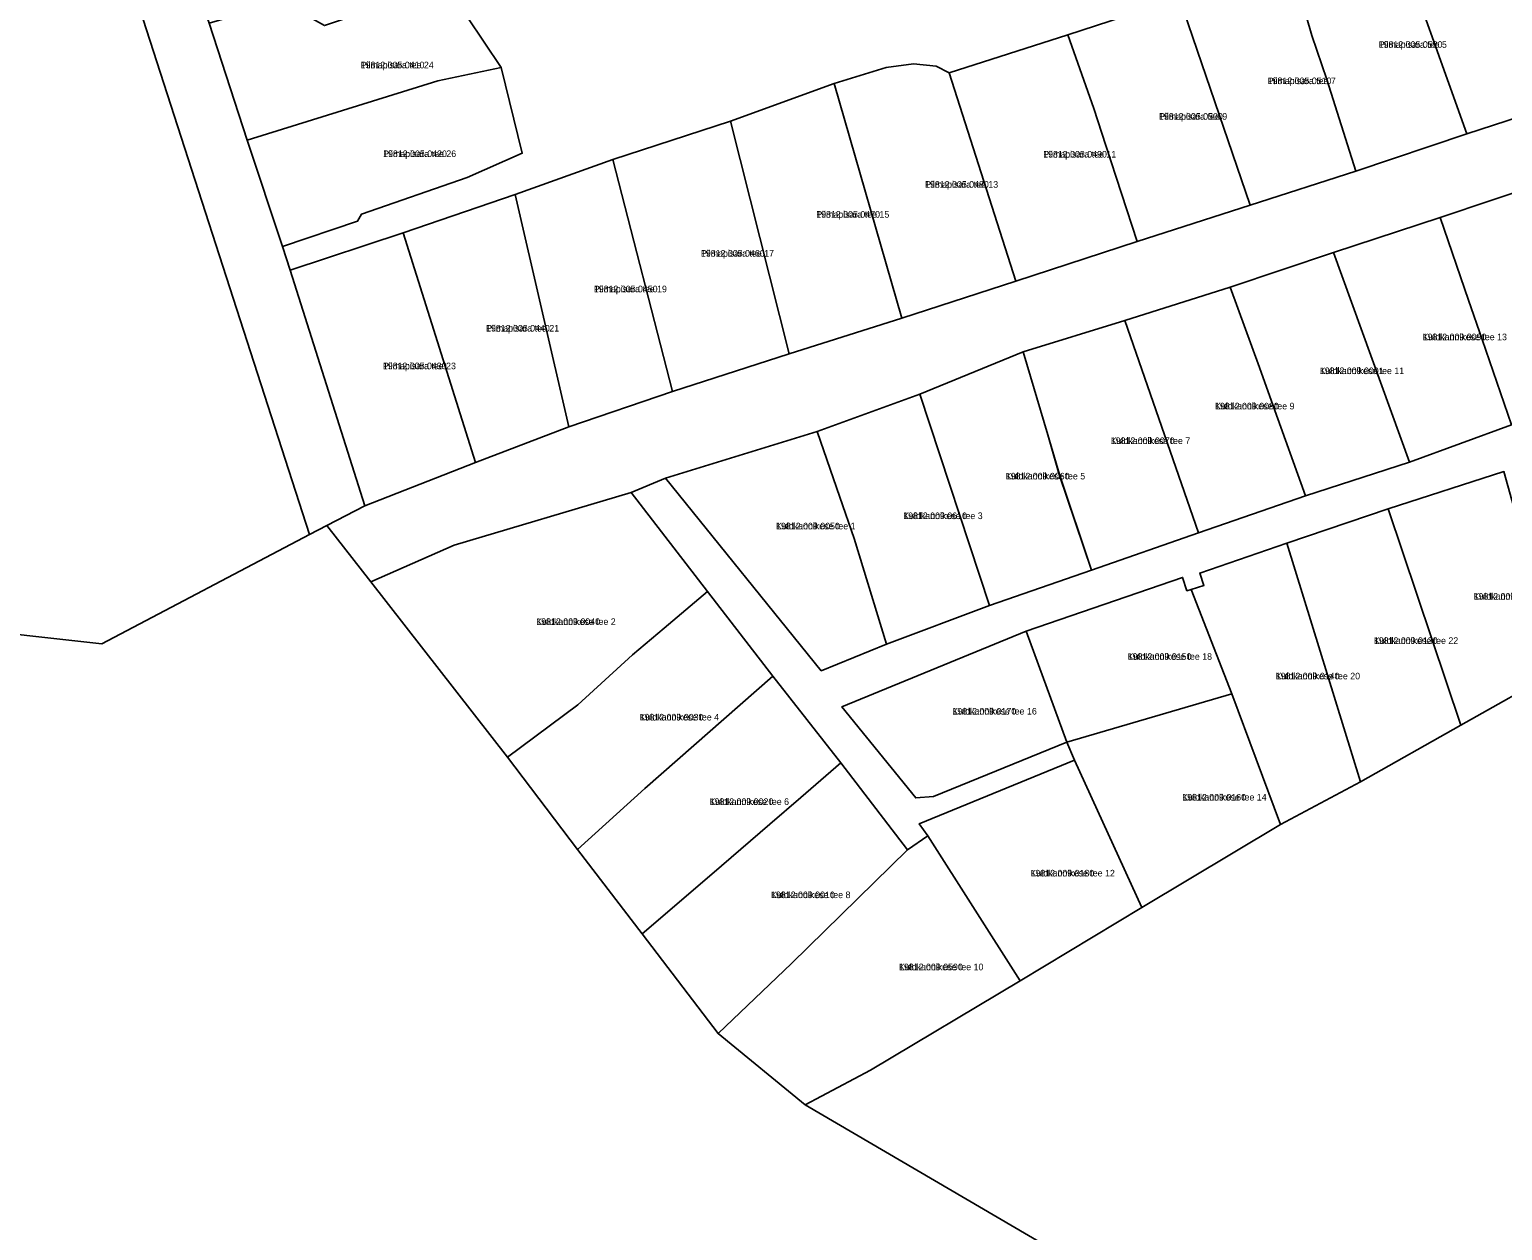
# Model space of a CAD drawing. Extents: x 516875 to 535633, y 6574491 to 6593094.
# Drawn here: x 517287.6 to 517622.6, y 6585054.3 to 6585327.5 of the extents above; entities that cross this region are included whole.
import ezdxf

# ---------------------------------------------------------------- set-up
doc = ezdxf.new("R2010")
doc.units = 0
for name, color, linetype in [('L_AADRESS', 7, 'Continuous'), ('PIIR', 7, 'Continuous'), ('TUNNUS', 7, 'Continuous')]:
    doc.layers.add(name, color=color, linetype=linetype)

msp = doc.modelspace()

# ---------------------------------------------------------------- linework, layer by layer
at = {"layer": 'PIIR'}
for points in [[(517363.93, 6585219.13), (517355.29, 6585214.67), (517351.33, 6585212.62), (517306.35, 6585351.92), (517308.83, 6585354.33), (517306.67, 6585359.47), (517261.59, 6585466.48), (517271.21, 6585468.82), (517305.11, 6585387.97), (517314.63, 6585364.95), (517317.95, 6585359.12), (517328.47, 6585328.95), (517337.16, 6585302.33), (517345.14, 6585278.12), (517346.9, 6585272.74)], [(517038.61, 6585356.85), (517061.8, 6585364.36), (517066.51, 6585412.44), (517103.89, 6585423.94), (517151.32, 6585438.55), (517221.5, 6585456.72), (517281.21, 6585332.08), (517282.72, 6585328.92), (517306.35, 6585351.92), (517351.33, 6585212.62), (517304.11, 6585187.79), (517235.26, 6585195.4), (517074.05, 6585291.89), (517021.05, 6585351.17)], [(517597.74, 6585350.7), (517621.4, 6585358.58), (517639.03, 6585311.71), (517614.54, 6585303.75)], [(517582.66, 6585316.09), (517579.3, 6585326.14), (517574.43, 6585343.02), (517597.74, 6585350.7), (517614.54, 6585303.75), (517589.29, 6585295.29)], [(517549.17, 6585334.61), (517574.43, 6585343.02), (517579.3, 6585326.14), (517582.66, 6585316.09), (517589.29, 6585295.29), (517565.22, 6585287.56)], [(517328.47, 6585328.95), (517348.36, 6585334.67), (517349.4, 6585331.37), (517354.69, 6585328.38), (517374.47, 6585334.99), (517387.15, 6585330.4), (517394.88, 6585318.83), (517380.48, 6585315.81), (517337.16, 6585302.33)], [(517532.39, 6585301.12), (517529.67, 6585309.52), (517523.81, 6585326.29), (517549.17, 6585334.61), (517565.22, 6585287.56), (517539.53, 6585279.24)], [(517496.81, 6585317.64), (517523.81, 6585326.29), (517529.67, 6585309.52), (517532.39, 6585301.12), (517539.53, 6585279.24), (517511.97, 6585270.23)], [(517470.66, 6585315.23), (517482.46, 6585318.86), (517488.71, 6585319.72), (517493.8, 6585319.19), (517496.81, 6585317.64), (517511.97, 6585270.23), (517486.02, 6585261.85)], [(517362.24, 6585283.93), (517345.14, 6585278.12), (517337.16, 6585302.33), (517380.48, 6585315.81), (517394.88, 6585318.83), (517399.68, 6585299.36), (517387.18, 6585293.81), (517363.13, 6585285.46)], [(517447.09, 6585306.65), (517470.66, 6585315.23), (517486.02, 6585261.85), (517460.4, 6585253.69)], [(517420.27, 6585297.94), (517447.09, 6585306.65), (517460.4, 6585253.69), (517433.9, 6585245.12)], [(517398.07, 6585289.93), (517420.27, 6585297.94), (517433.9, 6585245.12), (517410.31, 6585237.13)], [(517614.91, 6585265.96), (517608.44, 6585284.76), (517631.99, 6585292.6), (517648.45, 6585245.74), (517624.71, 6585237.55), (517618.01, 6585256.96)], [(517372.63, 6585281.26), (517398.07, 6585289.93), (517410.31, 6585237.13), (517389.09, 6585228.98)], [(517601.46, 6585229.09), (517584.2, 6585276.78), (517608.44, 6585284.76), (517614.91, 6585265.96), (517618.01, 6585256.96), (517624.71, 6585237.55)], [(517372.63, 6585281.26), (517389.09, 6585228.98), (517363.93, 6585219.13), (517346.9, 6585272.74)], [(517584.2, 6585276.78), (517601.46, 6585229.09), (517577.8, 6585221.42), (517570.49, 6585241.91), (517567.36, 6585250.58), (517560.73, 6585268.9)], [(517553.48, 6585213.04), (517536.73, 6585261.33), (517560.73, 6585268.9), (517567.36, 6585250.58), (517570.49, 6585241.91), (517577.8, 6585221.42)], [(517519.23, 6585235.31), (517513.62, 6585254.14), (517536.73, 6585261.33), (517553.48, 6585213.04), (517529.19, 6585204.53), (517521.91, 6585226.3)], [(517505.93, 6585196.48), (517490.14, 6585244.53), (517513.62, 6585254.14), (517519.23, 6585235.31), (517521.83, 6585226.3), (517529.19, 6585204.53)], [(517471.91, 6585221.15), (517466.75, 6585236.09), (517490.14, 6585244.53), (517505.93, 6585196.48), (517482.54, 6585187.67), (517475.16, 6585211.75)], [(517467.69, 6585181.64), (517432.31, 6585225.47), (517466.75, 6585236.09), (517471.91, 6585221.15), (517475.16, 6585211.75), (517482.54, 6585187.67)], [(517613.18, 6585169.29), (517596.62, 6585218.49), (517622.95, 6585226.93), (517635.49, 6585181.83)], [(517365.25, 6585201.88), (517384.23, 6585210.19), (517424.46, 6585222.17), (517441.82, 6585199.64), (517431.98, 6585191.3), (517424.8, 6585185.24), (517412.37, 6585173.91), (517396.34, 6585161.95)], [(517590.31, 6585156.36), (517573.58, 6585210.64), (517596.62, 6585218.49), (517613.18, 6585169.29)], [(517554.73, 6585200.99), (517553.8, 6585203.86), (517573.58, 6585210.64), (517590.31, 6585156.36), (517572.14, 6585146.66), (517561.08, 6585176.41), (517551.81, 6585200.13)], [(517523.54, 6585165.38), (517514.34, 6585190.62), (517549.87, 6585202.86), (517550.85, 6585199.83), (517551.81, 6585200.13), (517561.08, 6585176.41)], [(517396.34, 6585161.95), (517412.37, 6585173.91), (517424.8, 6585185.24), (517431.98, 6585191.3), (517441.82, 6585199.64), (517456.69, 6585180.4), (517427.6, 6585154.82), (517412.29, 6585140.99)], [(517489.18, 6585152.72), (517472.39, 6585173.45), (517514.34, 6585190.62), (517523.54, 6585165.38), (517493.26, 6585153.01)], [(517426.96, 6585121.82), (517412.29, 6585140.99), (517427.6, 6585154.82), (517456.69, 6585180.4), (517472.17, 6585160.72), (517463.07, 6585152.81), (517456.03, 6585146.73), (517442.8, 6585135.36)], [(517525.32, 6585161.27), (517523.54, 6585165.38), (517561.08, 6585176.41), (517572.14, 6585146.66), (517540.61, 6585127.8)], [(517487.31, 6585140.87), (517460.95, 6585115.01), (517444.25, 6585099.1), (517426.96, 6585121.82), (517442.8, 6585135.36), (517456.03, 6585146.73), (517463.07, 6585152.81), (517472.17, 6585160.72)], [(517491.97, 6585144.08), (517489.97, 6585146.82), (517525.32, 6585161.27), (517540.61, 6585127.8), (517512.94, 6585111.09)], [(517464.03, 6585082.92), (517444.25, 6585099.1), (517460.95, 6585115.01), (517487.31, 6585140.87), (517491.97, 6585144.08), (517512.94, 6585111.09), (517478.89, 6585090.76)]]:
    msp.add_lwpolyline(points, close=True, dxfattribs=at)
for points in [[(517549.17, 6585334.61), (517523.81, 6585326.29), (517496.81, 6585317.64), (517493.8, 6585319.19), (517488.71, 6585319.72), (517482.46, 6585318.86), (517470.66, 6585315.23), (517447.09, 6585306.65), (517420.27, 6585297.94), (517398.07, 6585289.93), (517372.63, 6585281.26), (517346.9, 6585272.74), (517345.14, 6585278.12), (517362.24, 6585283.93), (517363.13, 6585285.46), (517387.18, 6585293.81), (517399.68, 6585299.36), (517394.88, 6585318.83), (517387.15, 6585330.4)], [(517631.99, 6585292.6), (517608.44, 6585284.76), (517584.2, 6585276.78), (517560.73, 6585268.9), (517536.73, 6585261.33), (517513.62, 6585254.14), (517490.14, 6585244.53), (517466.75, 6585236.09), (517432.31, 6585225.47), (517424.46, 6585222.17), (517384.23, 6585210.19), (517365.25, 6585201.88), (517355.29, 6585214.67), (517363.93, 6585219.13), (517389.09, 6585228.98), (517410.31, 6585237.13), (517433.9, 6585245.12), (517460.4, 6585253.69), (517486.02, 6585261.85), (517511.97, 6585270.23), (517539.53, 6585279.24), (517565.22, 6585287.56), (517589.29, 6585295.29), (517614.54, 6585303.75), (517639.03, 6585311.71)], [(517622.95, 6585226.93), (517596.62, 6585218.49), (517573.58, 6585210.64), (517553.8, 6585203.86), (517554.73, 6585200.99), (517551.81, 6585200.13), (517550.85, 6585199.83), (517549.87, 6585202.86), (517514.34, 6585190.62), (517472.39, 6585173.45), (517489.18, 6585152.72), (517493.26, 6585153.01), (517523.54, 6585165.38), (517525.32, 6585161.27), (517489.97, 6585146.82), (517491.97, 6585144.08), (517487.31, 6585140.87), (517472.17, 6585160.72), (517456.69, 6585180.4), (517441.82, 6585199.64), (517424.46, 6585222.17), (517432.31, 6585225.47), (517467.69, 6585181.64), (517482.54, 6585187.67), (517505.93, 6585196.48), (517529.19, 6585204.53), (517553.48, 6585213.04), (517577.8, 6585221.42), (517601.46, 6585229.09), (517624.71, 6585237.55)], [(517544.27, 6585035.98), (517464.03, 6585082.92), (517478.89, 6585090.76), (517512.94, 6585111.09), (517540.61, 6585127.8), (517572.14, 6585146.66), (517590.31, 6585156.36), (517613.18, 6585169.29), (517635.49, 6585181.83), (517668.33, 6585200.39), (517680.96, 6585186.59), (517712.74, 6585158.59), (517720.29, 6585151.94), (517733.25, 6585135.93), (517745.59, 6585104.97), (517746.88, 6585080.89), (517782.89, 6585079.14), (517818.43, 6585077.45), (517852.74, 6585075.65), (517888.61, 6585073.72), (517925.17, 6585071.77), (517961.96, 6584867.62)]]:
    msp.add_lwpolyline(points, dxfattribs=at)

# ---------------------------------------------------------------- texts
at = {"layer": 'L_AADRESS'}
for s, p in [('Piimapisara tee 5', (517594.48, 6585323.33)), ('Piimapisara tee 24', (517362.95, 6585318.66)), ('Piimapisara tee 7', (517569.23, 6585315.07)), ('Piimapisara tee 9', (517544.52, 6585306.97)), ('Piimapisara tee 26', (517368.06, 6585298.48)), ('Piimapisara tee 11', (517518.17, 6585298.37)), ('Piimapisara tee 13', (517491.31, 6585291.5)), ('Piimapisara tee 15', (517466.56, 6585284.69)), ('Piimapisara tee 17', (517440.34, 6585275.83)), ('Piimapisara tee 19', (517415.98, 6585267.72)), ('Piimapisara tee 21', (517391.47, 6585258.79)), ('Kuldkannikese tee 13', (517604.46, 6585256.81)), ('Piimapisara tee 23', (517368, 6585250.22)), ('Kuldkannikese tee 11', (517581.09, 6585249.11)), ('Kuldkannikese tee 9', (517557.26, 6585241.08)), ('Kuldkannikese tee 7', (517533.55, 6585233.2)), ('Kuldkannikese tee 5', (517509.66, 6585225.15)), ('Kuldkannikese tee 1', (517457.43, 6585213.79)), ('Kuldkannikese tee 3', (517486.34, 6585216.13)), ('Kuldkannikese tee 24', (517616.05, 6585197.81)), ('Kuldkannikese tee 2', (517402.89, 6585192.06)), ('Kuldkannikese tee 22', (517593.38, 6585187.74)), ('Kuldkannikese tee 18', (517537.39, 6585184.12)), ('Kuldkannikese tee 20', (517571.06, 6585179.67)), ('Kuldkannikese tee 4', (517426.39, 6585170.32)), ('Kuldkannikese tee 16', (517497.54, 6585171.67)), ('Kuldkannikese tee 6', (517442.3, 6585151.11)), ('Kuldkannikese tee 14', (517549.81, 6585152.11)), ('Kuldkannikese tee 12', (517515.29, 6585134.84)), ('Kuldkannikese tee 8', (517456.28, 6585129.91)), ('Kuldkannikese tee 10', (517485.39, 6585113.5))]:
    msp.add_text(s, height=1.5, dxfattribs=at).set_placement(p)
at = {"layer": 'TUNNUS'}
for s, p in [('19812:005:0520', (517594.48, 6585323.33)), ('19812:005:0410', (517362.95, 6585318.66)), ('19812:005:0510', (517569.23, 6585315.07)), ('19812:005:0500', (517544.52, 6585306.97)), ('19812:005:0420', (517368.06, 6585298.48)), ('19812:005:0490', (517518.17, 6585298.37)), ('19812:005:0480', (517491.31, 6585291.5)), ('19812:005:0470', (517466.56, 6585284.69)), ('19812:005:0460', (517440.34, 6585275.83)), ('19812:005:0450', (517415.98, 6585267.72)), ('19812:005:0440', (517391.47, 6585258.79)), ('19812:009:0090', (517604.46, 6585256.81)), ('19812:005:0430', (517368, 6585250.22)), ('19812:009:0001', (517581.09, 6585249.11)), ('19812:009:0080', (517557.26, 6585241.08)), ('19812:009:0070', (517533.55, 6585233.2)), ('19812:009:0060', (517509.66, 6585225.15)), ('19812:009:0050', (517457.43, 6585213.79)), ('19812:009:0610', (517486.34, 6585216.13)), ('19812:009:0120', (517616.05, 6585197.81)), ('19812:009:0040', (517402.89, 6585192.06)), ('19812:009:0130', (517593.38, 6585187.74)), ('19812:009:0150', (517537.39, 6585184.12)), ('19812:009:0140', (517571.06, 6585179.67)), ('19812:009:0030', (517426.39, 6585170.32)), ('19812:009:0170', (517497.54, 6585171.67)), ('19812:009:0020', (517442.3, 6585151.11)), ('19812:009:0160', (517549.81, 6585152.11)), ('19812:009:0180', (517515.29, 6585134.84)), ('19812:009:0010', (517456.28, 6585129.91)), ('19812:009:0590', (517485.39, 6585113.5))]:
    msp.add_text(s, height=1.5, dxfattribs=at).set_placement(p)

doc.saveas('drawing.dxf')
